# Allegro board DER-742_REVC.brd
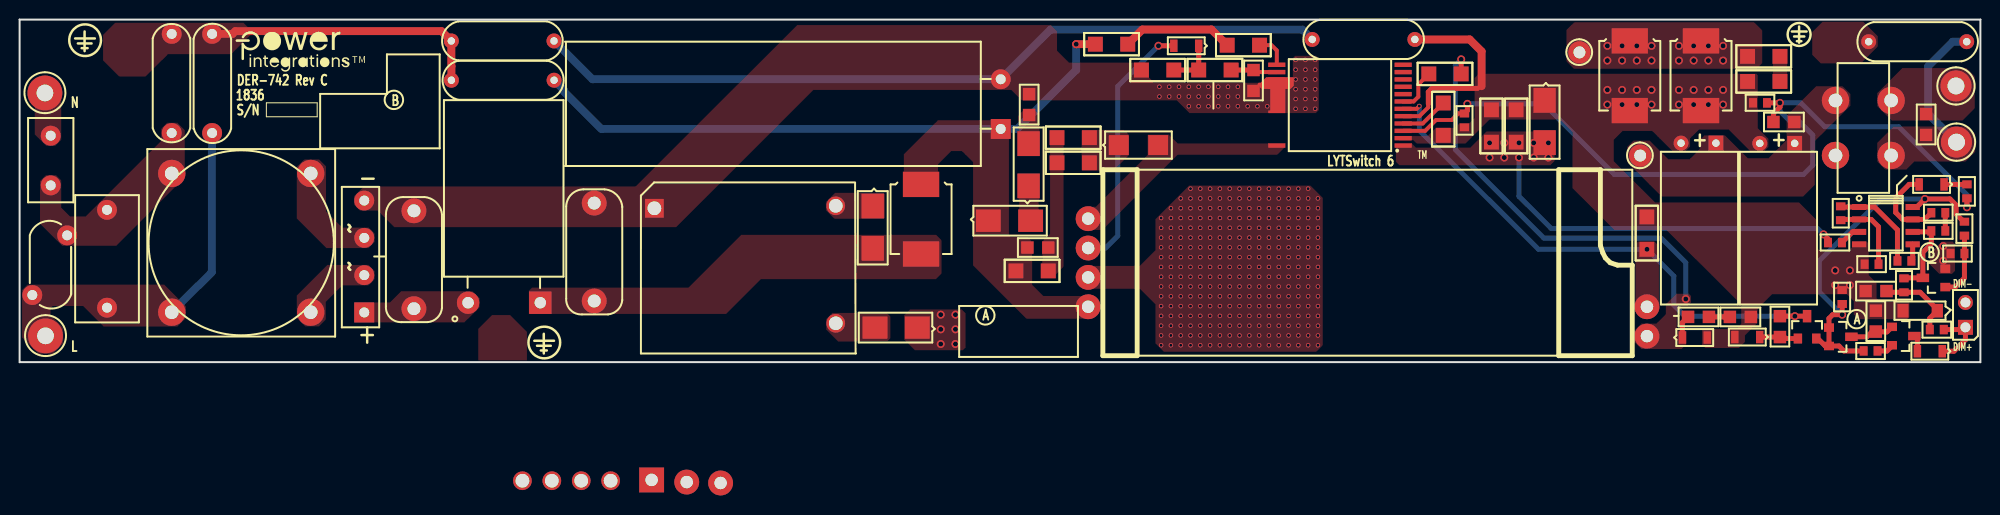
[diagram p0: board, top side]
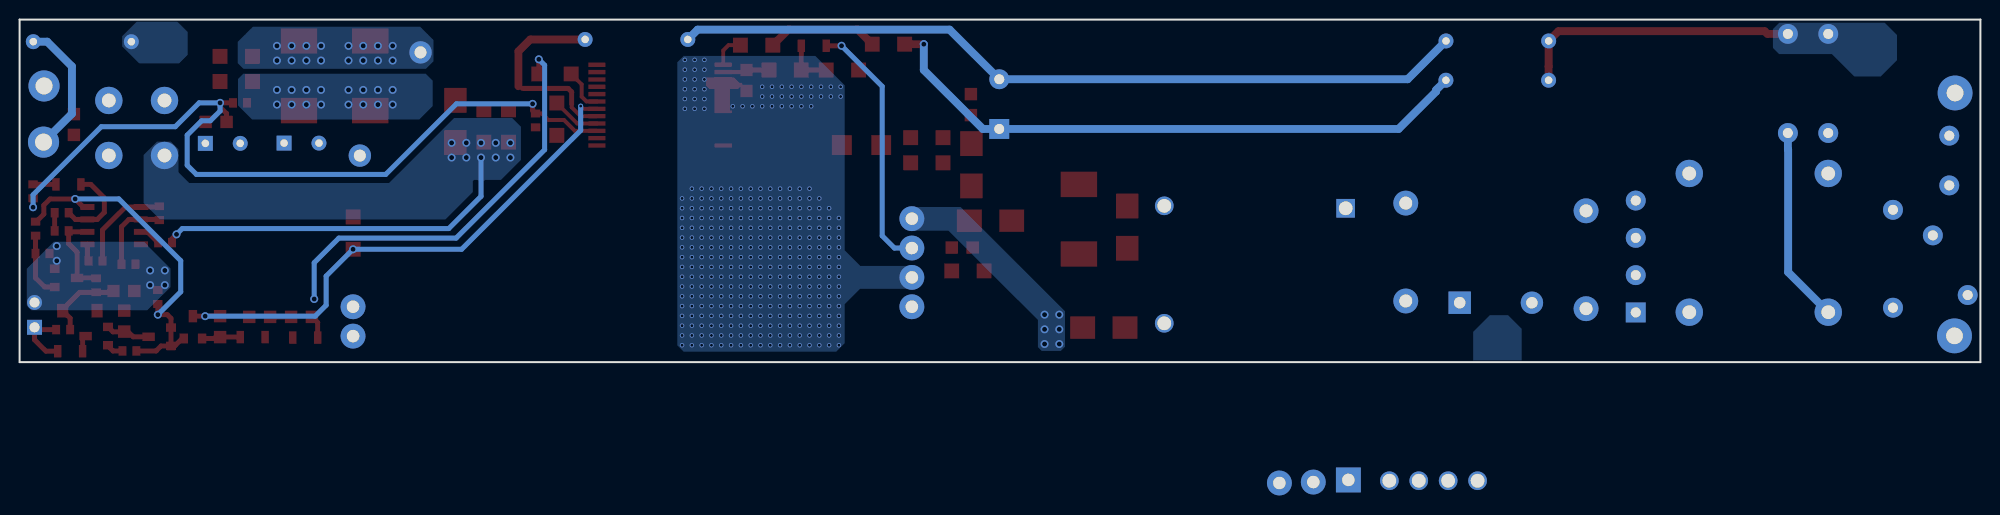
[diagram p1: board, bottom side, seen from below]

Outline 200 x 35 mm; copper layers: TOP, BOTTOM. Coordinates in mm from the lower left corner of the outline.
Outline path: 0,35 0,0 200,0 200,35 0,35

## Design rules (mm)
constraint set DEFAULT: min track width 0.508

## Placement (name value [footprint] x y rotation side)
BR1  UD4KB100-BP  [PIDAXBRIDGED3K]  35.15 5.08 90 top
C1  0.15 uF  [PINPXCAPRAD13X7LS10MMD040]  8.92 5.56 90 top
C2  220 nF  [PI_NP_CAPRAD512X299LS394D040]  40.22 5.46 90 top
C3  330 nF  [PI_NP_CAPRAD512X299LS394D040]  58.61 6.25 90 top
C4  68 uF  [PIPOLCAPCLYD500LS200040]  100.08 23.83 90 top
C9  3.3 nF  [PISMC0805]  104.92 11.71 180 top
C10  10uF  [PISMC1206]  117.73 29.84 180 top
C11  4.7 uF  [PISMC0805]  125.86 29.84 270 top
C12  2200 pF  [PINPCAPRAD9P0D10P0LS030]  132.08 32.97 0 top
C13  2.2 uF  [PISMC1206]  145.21 23.17 90 top
C14  220 pf  [PISMC1206]  179.55 28.68 180 top
C15  4.7 uF  [PISMC1206]  165.98 11.53 90 top
C16  100 uF  [PIPOLCAPCLYD320LS140030]  173.02 22.38 180 top
C18  100 uF  [PIPOLCAPCLYD320LS140030]  181.05 22.35 180 top
C19  330 pF  [PISMC0603]  147.37 23.99 90 top
C26  2.2 uF  [PISMC0805]  190.42 7.26 180 top
C28  1 uF  [PISMC0603]  196.42 13.41 180 top
C34  68 pF  [PINPYCAPRAD470X210LS380040]  19.64 23.65 90 top
C35  68 pF  [PINPYCAPRAD470X210LS380040]  15.52 33.3 270 top
C37  2.2 nF  [PISMC0805]  194.46 25.35 270 top
C38  220 pF  [PISMC0805]  174.45 4.62 0 top
C39  470 nF  [PISMC0603]  198.37 14.35 270 top
C40  100 nF  [PISMC0603]  185.9 7.37 270 top
C41  2200 pF  [PINPCAPRAD9P0D10P0LS030#2]  198.6 32.74 180 top
C42  2200 pF  [PINPCAPRAD9P0D10P0LS030]  54.28 28.8 180 top
C43  2200 pF  [PINPCAPRAD9P0D10P0LS030]  44.27 32.82 0 top
D1  ES1G-13-F  [PISMDO214AC12]  87.02 15.95 270 top
D7  BAV21WS-7-F  [PISMSOD323]  120.27 32.32 180 top
D8  S1K  [PISMDSMA]  112.12 22.18 0 top
D9  BAV16WS-7-F  [PISMSOD323]  196.29 18.16 180 top
D10  STTH3R04S  [PISMDO214AB12]  171.5 32.82 270 top
D11  BAV21WS-7-F  [PISMSOD323]  169.6 2.51 0 top
D16  S3J-13-F  [PISMDO214AB12]  91.95 18.16 270 top
D17  ES1G-13-F  [PISMDO214AC12]  91.57 3.53 180 top
D18  STTH3R04S  [PISMDO214AB12]  164.24 32.82 270 top
D19  BAV19WS  [PISMSOD323]  196.11 1.12 180 top
D21  B340A-13-F  [PISMDO214AC12]  155.55 26.75 270 top
F1  3.15 A  [PI_RST_MICROFUSE]  3.17 23.14 270 top
FL1  Hole_50mils  [PI_HOLE_50MIL]  165.3 21.1 0 top
FL2  Hole_50mils  [PI_HOLE_50MIL]  159.11 31.65 0 top
J4  CON2  [PIMOLEX2KKHEADER]  198.48 3.56 90 top
L1  20mH  [PI_IND_4P_690X512LS300X200D055#2]  20.07 16 0 top
L3  680 uh  [PI_CHOKE_RL5480-4_D2]  53.11 6.07 180 top
L4  200uH  [PI_IND_4P_690X512LS300X200D055]  185.52 27.74 0 top
NOREF  -  []  0 0 90 top
NOREF#2  -  []  22.05 34.24 0 top
NOREF#3  -  []  0 35 0 top
Q2  MMBT4401LT1G  [PISMSOT23123_1]  183.26 2.41 0 top
Q10  MMBT3906  [PISMSOT23123_1]  190.98 1.73 270 top
Q11  2N7002  [PISMSOT23123_1]  196.42 9.55 90 top
R4  2.00 M  [PISMR1206]  113.03 32.49 180 top
R14  71.5 k  [PISMR0603]  198.63 18.16 270 top
R17  120 k  [PISMR1206]  101.62 9.32 0 top
R18  10 k  [PISMR1206]  120.27 29.84 0 top
R19  1 k  [PISMR0603]  192.2 7.14 90 top
R20  20 k  [PISMR0603]  194.84 3.33 0 top
R22  47  [PISMR1206]  147.04 29.45 180 top
R23  22  [PISMR1206]  179.55 31.24 180 top
R24  0.068  [PISMR1206]  150.13 22.48 90 top
R29  100 k  [PISMR0805]  181.03 24.54 180 top
R30  3.09 k  [PISMR0603]  178.23 26.49 180 top
R34  1 k  [PISMR0603]  196.42 15.27 180 top
R45  2.00 M  [PISMR1206]  126.48 32.38 180 top
R46  20  [PISMR1206]  105.82 20.37 0 top
R47  10 k  [PISMR0805]  102.97 25.25 90 top
R50  20  [PISMR1206]  105.82 22.93 0 top
R51  0.068  [PISMR1206]  152.64 22.48 90 top
R52  22  [PISMR0805]  170.18 4.62 0 top
R62  1 k  [PISMR0603]  192.96 10.34 180 top
R63  261 k  [PISMR0603]  185.75 14.5 90 top
R64  9.1 k  [PISMR0805]  189.33 5.26 270 top
R65  5.1 k  [PISMR0603]  196.95 11.1 0 top
R66  6.34 k  [PISMR0603]  188.09 1.14 0 top
R71  909  [PISMR0603]  189.61 10.01 180 top
R73  2.21 k  [PISMR0805]  179.55 4.7 270 top
R74  909  [PISMR0603]  185.88 12.22 180 top
RTN  PCB Terminal 18 AWG  [PI_HOLE_18AWG]  197.56 22.45 0 top
RV1  275 Vac  [PIDISC350X160LS210X140040]  4.85 12.95 270 top
T1  EPC1716D  [PI_BOBBIN_EPC1716D_7P]  64.75 15.72 0 top
T2  EDR4110  [PI_BOBBIN_EDR4110_9P_6X3]  137.49 10.16 0 top
TP1  BLK  [PITPKEYSTONE125X125]  2.64 2.69 180 top
TP2  WHT  [PITPKEYSTONE125X125]  2.58 27.5 180 top
U4  LYT6068C  [PI_IC_INSOP_24D]  141.12 22.13 180 top
U8  LMV431AIMF  [PISMSOT23132]  184.56 1.65 270 top
U14  TSX712IDT  [PISMSO8]  187.63 15.85 270 top
VOUT  PCB Terminal 18 AWG  [PI_HOLE_18AWG]  197.51 28.19 0 top
VR2  1SMA200Z  [PISMDO214AC12]  98.81 14.45 0 top
VR3  1SMA200Z  [PISMDO214AC12]  102.92 18.01 90 top
VR5  BZT52C15-7-F  [PI_SM_SOD-123_12]  195.61 5.26 180 top
VR6  BZX384-B13,115  [PISMSOD323]  177.5 2.57 180 top

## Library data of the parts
BR1 = DISCRETE BRIDGE_+~~-: alternate symbols: (pidaxbridgeD3K_horz)
C1 = CAP NP: alternate symbols: (pinpxcaprad13x7LS10mmD040H)
C2 C3 = CAP NP: alternate symbols: (pi_np_caprad512x299ls394d040_h)
C4 = CAP POL: alternate symbols: (pipolcapclyd500ls2000401650lh)
C9-C15 C19 C34 C35 C37 C38 C41-C43 = CAP NP
C16 C18 = CAP POL
C26 C28 C39 C40 = CAP NP: room: 4
D1 D7-D11 D16-D19 = DIODE
D21 = DIODE SCHOTTKY
F1 = FUSE: alternate symbols: (pirstmicrofusehoz)
FL1 FL2 = FlyingLead
J4 = CON2
L1 L4 = INDUCTOR_4P_revD: alternate symbols: (pi_4p_700x400d055_horiz)
L3 = INDUCTOR_dot2: alternate symbols: (pi_choke_RL5480-4H_d2)
Q2 = NPN_BEC
Q10 = PNP_BEC
Q11 = FET_N_GSD
R4 R17 R18 R22-R24 R29 R30 R45-R47 R50-R52 R64 R66 R73 = R
R14 R19 R20 R34 R62 R63 R65 R71 R74 = R: room: 1
RTN VOUT = TERM_1Pin
RV1 = VARISTOR: alternate symbols: (pi_disc_354x220_ls220x10_040_h)
T1 = BEFD18_7P
T2 = BEQ20_9P
TP1 TP2 = TESTPOINT
U4 = LYT6
U8 = TL431/SOT-23_RCA
U14 = TSX712IDT
VR2 VR3 VR5 VR6 = DIODE_ZENER

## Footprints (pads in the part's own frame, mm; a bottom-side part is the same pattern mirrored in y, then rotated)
PI_BOBBIN_EDR4110_9P_6X3
  rect 2.54x2.54 hole 1.27: 1(-73.026,-22.193)
  round 2.54 hole 1.27: 2(-28.5,4.5) 3(-28.5,1.5) 4(-28.5,-1.5) 5(-28.5,-4.5) 6(-69.445,-22.41) 7(28.5,-7.5) 8(28.5,-4.5) 9(-65.988,-22.506)
PI_BOBBIN_EPC1716D_7P
  rect 1.905x1.905 hole 1.397: 1(0,0)
  round 1.905 hole 1.397: 2(-13.46,-27.836) 3(-10.46,-27.836) 4(-7.46,-27.836) 5(-4.46,-27.836) 6(18.5,-11.75) 7(18.5,0.25)
PI_CHOKE_RL5480-4_D2
  rect 2.286x2.286 hole 1.168: 1(0,0)
  round 2.286 hole 1.168: 2(7.366,0)
PI_HOLE_18AWG
  round 3.175 hole 1.727: 1(0,0.025)
PI_HOLE_50MIL
  round 2.286 hole 1.219: 1(0,0)
PI_IC_INSOP_24D
  rect 1.75x0.45 smd: 1(0,0) 2(0,-0.75) 3(0,-1.5) 4(0,-2.25) 5(0,-3) 6(0,-3.75) 7(0,-4.5) 8(0,-5.25) 9(0,-6) 10(0,-6.75) 11(0,-7.5) 12(0,-8.25) 13(12.89,-8.25) 14(12.89,-7.5) 15(12.89,-6.75) 24(12.89,0)
  custom 0.438x0.438 smd: 16(12.89,-4.67)
PI_IND_4P_690X512LS300X200D055
  round 2.794 hole 1.397: 1(-0.3,-1) 2(5.38,-1) 3(5.38,-6.62) 4(-0.3,-6.62)
PI_IND_4P_690X512LS300X200D055#2
  round 2.794 hole 1.397: 1(-4.547,3.277) 2(9.627,3.277) 3(9.627,-10.897) 4(-4.547,-10.897)
PI_NP_CAPRAD512X299LS394D040
  round 2.54 hole 1.321: 1(0,0) 2(10,0)
PI_RST_MICROFUSE
  round 2.032 hole 1.016: 1(0,0) 2(5.08,0)
PI_SM_SOD-123_12
  rect 1.143x1.397 smd: 1(0,0) 2(3.505,0)
PIDAXBRIDGED3K
  rect 2.032x2.032 hole 1.016: 1(0,0)
  round 2.032 hole 1.016: 2(3.81,0) 3(7.62,0) 4(11.43,0)
PIDISC350X160LS210X140040
  round 2.032 hole 1.016: 1(0,0) 2(6.096,-3.556)
PIMOLEX2KKHEADER
  rect 1.524x1.524 hole 1.016: 1(0,0)
  round 1.524 hole 1.016: 2(2.54,0)
PINPCAPRAD9P0D10P0LS030
  round 1.524 hole 0.762: 1(-0.236,0) 2(10.236,0)
PINPCAPRAD9P0D10P0LS030#2
  round 1.524 hole 0.762: 1(0,0) 2(10,0)
PINPXCAPRAD13X7LS10MMD040
  round 2.032 hole 1.016: 1(0,0) 2(10,0)
PINPYCAPRAD470X210LS380040
  round 2.032 hole 1.016: 1(-0.236,0) 2(9.888,0)
PIPOLCAPCLYD320LS140030
  rect 1.524x1.524 hole 0.762: 1(0,0)
  round 1.524 hole 0.762: 2(3.556,0)
PIPOLCAPCLYD500LS200040
  rect 2.032x2.032 hole 1.016: 1(0,0)
  round 2.032 hole 1.016: 2(5.08,0)
PISMC0603
  rect 0.813x0.965 smd: 1(0,0) 2(1.422,0)
PISMC0805
  rect 1.27x1.27 smd: 1(0,0) 2(2.134,0)
PISMC1206
  rect 1.524x1.524 smd: 1(0,0) 2(3.302,0)
PISMDO214AB12
  rect 2.591x3.708 smd: 1(0,0) 2(7.112,0)
PISMDO214AC12
  rect 2.54x2.286 smd: 1(0,0) 2(4.318,0)
PISMDSMA
  rect 2.032x2.032 smd: 1(0,0) 2(4.013,0)
PISMR0603
  rect 0.813x0.965 smd: 1(0,0) 2(1.422,0)
PISMR0805
  rect 1.27x1.27 smd: 1(0,0) 2(2.134,0)
PISMR1206
  rect 1.524x1.524 smd: 1(0,0) 2(3.302,0)
PISMSO8
  rect 0.61x1.448 smd: 1(0,0) 2(1.27,0) 3(2.54,0) 4(3.81,0) 5(3.81,5.461) 6(2.54,5.461) 7(1.27,5.461) 8(0,5.461)
PISMSOD323
  rect 0.762x1.27 smd: 1(0,0) 2(2.54,0)
PISMSOT23123_1
  rect 0.864x1.016 smd: 1(-1.88,0) 2(0,0)
  rect 0.864x1.27 smd: 3(-0.94,2.286)
PISMSOT23132
  rect 0.864x1.016 smd: 1(-1.88,0) 2(0,0)
  rect 0.864x1.27 smd: 3(-0.94,2.286)
PITPKEYSTONE125X125
  round 3.556 hole 1.702: 1(0,0)

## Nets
GND: C12.2 C13.1 C14.2 C15.2 C16.2 C18.2 C19.1 C26.2 C38.2 C40.1 D10.2 D11.2 D18.2 D21.1 J4.2 Q11.2(S) R24.2 R30.2 R51.2 R64.1 R65.1 R71.2 U4.2 U4.5 U14.4 VR5.2 VR6.2
GND_EARTH: C34.2 C35.1 C41.2 C42.2 C43.1
NC8: U4.8
NC9: U4.9
NC10: U4.10
NC11: U4.11
NC12: U4.12
NC15: U4.15
PIN7: D11.1 R22.1 R52.1 T2.7
PIN8: C15.1 Q2.3 R73.1 T2.8 U4.6
PWM: D19.1 J4.1 R20.2
V_AUX: C39.1 C40.2 Q2.2(EMITTER) R66.1 U8.1(VREF) U8.2 U14.8
N10967118: C10.1 D7.1 R18.1
N10967192: D8.1 R46.2 R50.2
N10967272: D8.2 D17.1 T2.2 U4.24
N10967292: C4.1 C9.2 C42.1 D16.1 R4.2 R17.1 T2.5 VR2.1
N10967352: C11.1 R18.2 U4.14
N10967360: C19.2 R14.2 R29.2 R30.1 U4.3
N10967588: C16.1 C18.1 FL1.1 L4.1 R29.1
N10967616: D10.1 D18.1 FL2.1 R23.2
N10968210: C14.1 R23.1
N10968562: BR1.4 C2.2 C3.2 C4.2 C10.2 C11.2 C12.1 C43.2 R47.2 T1.1 T2.4 U4.16
N10970513: C1.2 C35.2 F1.2 L1.1 RV1.1
N10971255: BR1.3(AC2) L1.2
N10975943: C9.1 R17.2 R46.1 R50.1
N11207739: C1.1 C34.1 L1.4 RV1.2 TP1.1
N11231482: R22.2 U4.7
N11317958: R45.1 U4.13(VPIN)
N11319179: C13.2 U4.4
N11446006: D1.1 T1.7
N11450999: C3.1 D1.2 D16.2 L3.1
N11459929: BR1.1 C2.1 L3.2
N11465077: F1.1 TP2.1
N11478809: VR2.2 VR3.1
N11478836: R47.1 VR3.2
N11497112: C38.1 R52.2
N11921550: Q10.2(EMITTER) R66.2
N11921594: Q10.1 R64.2 U8.3
N11921660: C39.2 Q11.1 R65.2
N11921664: D19.2 Q10.3
N11921668: D9.2 R34.2 U14.7(OUT)
N11921676: C28.1 R34.1
N11921680: C28.2 Q11.3 R19.2 U14.6
N11921778: R62.1 U14.5
N11921790: D9.1 R14.1
N11921854: C26.1 R19.1 R20.1 VR5.1
N11922118: R62.2 R63.2 U14.1
N11922154: R63.1 R71.1 U14.2
N11926287: C37.1 L4.2 VOUT.1
N11926309: C37.2 C41.1 L4.3 RTN.1
N11929315: R4.1 R45.2
N11931425: D7.2 T2.3
N11945881: D21.2 L4.4 R24.1 R51.1 R74.2 U4.1
N11960452: R74.1 U14.3
N12237167: D17.2 T1.6
N12249644: Q2.1 R73.2 VR6.1
N12296601: BR1.2 L1.3

Pads without a net: T1 2 3 4 5; T2 1 6 9

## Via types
v1: diameter 0.813, hole 0.508, TOP to BOTTOM, 66 vias
v2: diameter 0.457, hole 0.305, TOP to BOTTOM, 328 vias

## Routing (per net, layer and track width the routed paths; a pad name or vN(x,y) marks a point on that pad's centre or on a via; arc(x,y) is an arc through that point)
GND: length 20.6
  TOP w0.4: U4.5 142.79,25.13 143.69,26.04 143.69,26.39
  TOP w0.508: 148.72,27.97 144.04,27.97 143.69,27.61 143.69,26.39
  TOP w0.8: C12.2 147.9,32.97 149.12,31.75 149.12,28.19
  vias: v1(161.95,27.81) v1(161.95,26.31) v1(163.45,27.81) v1(163.45,26.31) v1(164.95,27.81) v1(164.95,26.31) v1(166.45,27.81) v1(166.45,26.31) v1(169.25,27.81) v1(169.25,26.31) v1(170.75,27.81) v1(170.75,26.31) v1(172.25,27.81) v1(172.25,26.31) v1(173.75,27.81) v1(173.75,26.31) v1(185.19,9.37) v1(185.19,7.87) v1(186.69,9.37) v1(186.69,7.87) v1(196.21,11.86) v1(196.21,10.36)
GND_EARTH: length 28.9
  TOP w0.8: C34.2 21.72,33.54 22,33.82 43.03,33.82 C43.1 44.04,30.23 44.04,30.22 C42.2
PIN7: length 45.3
  TOP w0.508: R52.1 169.6,4.04 D11.1 ; v1(147.04,30.94) R22.1
  BOTTOM w0.508: v1(169.95,6.45) 169.95,10.16 167.44,12.67 155.47,12.67 146.45,21.7 146.45,30.34 v1(147.04,30.94)
PIN8: length 54.9
  TOP w0.4: v2(142.77,26.16) 142.49,25.88 U4.6
  TOP w0.508: Q2.3 v1(181.08,4.7) R73.1
  BOTTOM w0.508: v2(142.77,26.16) 142.77,23.67 154.91,11.53 v1(165.99,11.53) 168.73,8.79 168.73,5.82 169.85,4.7 v1(181.08,4.7)
PWM: length 6.4
  TOP w0.508: D19.1 197.3,1.12 198.48,2.29 J4.1 198.24,3.33 R20.2
V_AUX: length 37.8
  TOP w0.508: U8.2 184.18,1.65 183.41,2.41 Q2.2 ; U8.2 185.57,1.65 186.08,1.14 R66.1 ; U8.2 U8.1 184.56,4.47 184.94,4.85 v1(185.9,4.85) C40.2 ; U14.8 193.51,15.85 v1(194.34,16.68) 196.89,16.68 197.53,16.04 197.53,15.12 198.3,14.35 C39.1
  BOTTOM w0.508: v1(185.9,4.85) 183.57,7.19 183.57,10.36 189.88,16.68 v1(194.34,16.68)
N10967118: length 5
  TOP w0.508: C10.1 R18.1 D7.1
N10967272:
  vias: v1(93.95,4.85) v1(93.95,3.35) v1(93.95,1.85) v1(95.45,4.85) v1(95.45,3.35) v1(95.45,1.85)
N10967292: length 62.5
  TOP w0.8: R4.2 v1(107.77,32.49)
  BOTTOM w0.8: C42.1 55.52,27.8 55.52,27.65 59.34,23.83 C4.1 101.75,23.83 107.77,29.85 v1(107.77,32.49)
N10967352: length 4.7
  TOP w0.4: U4.14 126.07,29.63 C11.1
  TOP w0.508: C11.1 R18.2
N10967360: length 83.7
  TOP w0.4: U4.3 143.37,23.63 144.48,24.74 146.08,24.74 146.75,25.41 C19.2
  TOP w0.508: C19.2 147.68,25.71 v1(147.68,26.39) ; R30.1 v1(179.55,26.49) 179.55,26.06 178.89,25.4 R29.2 ; R14.2 v1(198.63,15.82)
  BOTTOM w0.508: v1(198.63,15.82) 198.63,17.09 191.67,24.05 184.12,24.05 181.69,26.49 v1(179.55,26.49) 179.55,25.65 180.54,24.66 181.43,24.66 182.91,23.19 182.91,20.12 181.97,19.18 162.66,19.18 155.45,26.39 v1(147.68,26.39)
N10967616:
  vias: v1(161.95,32.31) v1(161.95,30.81) v1(163.45,32.31) v1(163.45,30.81) v1(164.95,32.31) v1(164.95,30.81) v1(166.45,32.31) v1(166.45,30.81) v1(169.25,32.31) v1(169.25,30.81) v1(170.75,32.31) v1(170.75,30.81) v1(172.25,32.31) v1(172.25,30.81) v1(173.75,32.31) v1(173.75,30.81)
N10968562: length 81.5
  BOTTOM w0.8: C43.2 58.42,28.91 C4.2 105.14,33.97 130.84,33.97 C12.1
  vias: v2(116.26,28.14) v2(116.26,27.14) v2(116.43,14.73) v2(116.43,13.73) v2(116.43,12.73) v2(116.43,11.73) v2(116.43,10.73) v2(116.43,9.73) v2(116.43,8.73) v2(116.43,7.73) v2(116.43,6.73) v2(116.43,5.73) v2(116.43,4.73) v2(116.43,3.73) v2(116.43,2.73) v2(116.43,1.73) v2(117.26,28.14) v2(117.26,27.14) v2(117.43,15.73) v2(117.43,14.73) v2(117.43,13.73) v2(117.43,12.73) v2(117.43,11.73) v2(117.43,10.73) v2(117.43,9.73) v2(117.43,8.73) v2(117.43,7.73) v2(117.43,6.73) v2(117.43,5.73) v2(117.43,4.73) v2(117.43,3.73) v2(117.43,2.73) v2(117.43,1.73) v2(118.26,28.14) v2(118.26,27.14) v2(118.43,16.73) v2(118.43,15.73) v2(118.43,14.73) v2(118.43,13.73) v2(118.43,12.73) v2(118.43,11.73) v2(118.43,10.73) v2(118.43,9.73) v2(118.43,8.73) v2(118.43,7.73) v2(118.43,6.73) v2(118.43,5.73) v2(118.43,4.73) v2(118.43,3.73) v2(118.43,2.73) v2(118.43,1.73) v2(119.26,28.14) v2(119.26,27.14) v2(119.26,26.14) v2(119.43,17.73) v2(119.43,16.73) v2(119.43,15.73) v2(119.43,14.73) v2(119.43,13.73) v2(119.43,12.73) v2(119.43,11.73) v2(119.43,10.73) v2(119.43,9.73) v2(119.43,8.73) v2(119.43,7.73) v2(119.43,6.73) v2(119.43,5.73) v2(119.43,4.73) v2(119.43,3.73) v2(119.43,2.73) v2(119.43,1.73) v2(120.26,28.14) v2(120.26,27.14) v2(120.26,26.14) v2(120.43,17.73) v2(120.43,16.73) v2(120.43,15.73) v2(120.43,14.73) v2(120.43,13.73) v2(120.43,12.73) v2(120.43,11.73) v2(120.43,10.73) v2(120.43,9.73) v2(120.43,8.73) v2(120.43,7.73) v2(120.43,6.73) v2(120.43,5.73) v2(120.43,4.73) v2(120.43,3.73) v2(120.43,2.73) v2(120.43,1.73) v2(121.26,28.14) v2(121.26,27.14) v2(121.26,26.14) v2(121.43,17.73) v2(121.43,16.73) v2(121.43,15.73) v2(121.43,14.73) v2(121.43,13.73) v2(121.43,12.73) v2(121.43,11.73) v2(121.43,10.73) v2(121.43,9.73) v2(121.43,8.73) v2(121.43,7.73) v2(121.43,6.73) v2(121.43,5.73) v2(121.43,4.73) v2(121.43,3.73) v2(121.43,2.73) v2(121.43,1.73) v2(122.26,28.14) v2(122.26,27.14) v2(122.26,26.14) v2(122.43,17.73) v2(122.43,16.73) v2(122.43,15.73) v2(122.43,14.73) v2(122.43,13.73) v2(122.43,12.73) v2(122.43,11.73) v2(122.43,10.73) v2(122.43,9.73) v2(122.43,8.73) v2(122.43,7.73) v2(122.43,6.73) v2(122.43,5.73) v2(122.43,4.73) v2(122.43,3.73) v2(122.43,2.73) v2(122.43,1.73) v2(123.26,28.14) v2(123.26,27.14) v2(123.26,26.14) v2(123.43,17.73) v2(123.43,16.73) v2(123.43,15.73) v2(123.43,14.73) v2(123.43,13.73) v2(123.43,12.73) v2(123.43,11.73) v2(123.43,10.73) v2(123.43,9.73) v2(123.43,8.73) v2(123.43,7.73) v2(123.43,6.73) v2(123.43,5.73) v2(123.43,4.73) v2(123.43,3.73) v2(123.43,2.73) v2(123.43,1.73) v2(124.26,28.14) v2(124.26,27.14) v2(124.26,26.14) v2(124.43,17.73) v2(124.43,16.73) v2(124.43,15.73) v2(124.43,14.73) v2(124.43,13.73) v2(124.43,12.73) v2(124.43,11.73) v2(124.43,10.73) v2(124.43,9.73) v2(124.43,8.73) v2(124.43,7.73) v2(124.43,6.73) v2(124.43,5.73) v2(124.43,4.73) v2(124.43,3.73) v2(124.43,2.73) v2(124.43,1.73) v2(125.26,26.14) v2(125.43,17.73) v2(125.43,16.73) v2(125.43,15.73) v2(125.43,14.73) v2(125.43,13.73) v2(125.43,12.73) v2(125.43,11.73) v2(125.43,10.73) v2(125.43,9.73) v2(125.43,8.73) v2(125.43,7.73) v2(125.43,6.73) v2(125.43,5.73) v2(125.43,4.73) v2(125.43,3.73) v2(125.43,2.73) v2(125.43,1.73) v2(126.26,26.14) v2(126.43,17.73) v2(126.43,16.73) v2(126.43,15.73) v2(126.43,14.73) v2(126.43,13.73) v2(126.43,12.73) v2(126.43,11.73) v2(126.43,10.73) v2(126.43,9.73) v2(126.43,8.73) v2(126.43,7.73) v2(126.43,6.73) v2(126.43,5.73) v2(126.43,4.73) v2(126.43,3.73) v2(126.43,2.73) v2(126.43,1.73) v2(127.26,26.14) v2(127.43,17.73) v2(127.43,16.73) v2(127.43,15.73) v2(127.43,14.73) v2(127.43,13.73) v2(127.43,12.73) v2(127.43,11.73) v2(127.43,10.73) v2(127.43,9.73) v2(127.43,8.73) v2(127.43,7.73) v2(127.43,6.73) v2(127.43,5.73) v2(127.43,4.73) v2(127.43,3.73) v2(127.43,2.73) v2(127.43,1.73) v2(128.43,17.73) v2(128.43,16.73) v2(128.43,15.73) v2(128.43,14.73) v2(128.43,13.73) v2(128.43,12.73) v2(128.43,11.73) v2(128.43,10.73) v2(128.43,9.73) v2(128.43,8.73) v2(128.43,7.73) v2(128.43,6.73) v2(128.43,5.73) v2(128.43,4.73) v2(128.43,3.73) v2(128.43,2.73) v2(128.43,1.73) v2(129.43,17.73) v2(129.43,16.73) v2(129.43,15.73) v2(129.43,14.73) v2(129.43,13.73) v2(129.43,12.73) v2(129.43,11.73) v2(129.43,10.73) v2(129.43,9.73) v2(129.43,8.73) v2(129.43,7.73) v2(129.43,6.73) v2(129.43,5.73) v2(129.43,4.73) v2(129.43,3.73) v2(129.43,2.73) v2(129.43,1.73) v2(130.15,30.88) v2(130.15,29.88) v2(130.15,28.88) v2(130.15,27.88) v2(130.15,26.88) v2(130.15,25.88) v2(130.43,17.73) v2(130.43,16.73) v2(130.43,15.73) v2(130.43,14.73) v2(130.43,13.73) v2(130.43,12.73) v2(130.43,11.73) v2(130.43,10.73) v2(130.43,9.73) v2(130.43,8.73) v2(130.43,7.73) v2(130.43,6.73) v2(130.43,5.73) v2(130.43,4.73) v2(130.43,3.73) v2(130.43,2.73) v2(130.43,1.73) v2(131.15,30.88) v2(131.15,29.88) v2(131.15,28.88) v2(131.15,27.88) v2(131.15,26.88) v2(131.15,25.88) v2(131.43,17.73) v2(131.43,16.73) v2(131.43,15.73) v2(131.43,14.73) v2(131.43,13.73) v2(131.43,12.73) v2(131.43,11.73) v2(131.43,10.73) v2(131.43,9.73) v2(131.43,8.73) v2(131.43,7.73) v2(131.43,6.73) v2(131.43,5.73) v2(131.43,4.73) v2(131.43,3.73) v2(131.43,2.73) v2(131.43,1.73) v2(132.15,30.88) v2(132.15,29.88) v2(132.15,28.88) v2(132.15,27.88) v2(132.15,26.88) v2(132.15,25.88) v2(132.43,16.73) v2(132.43,15.73) v2(132.43,14.73) v2(132.43,13.73) v2(132.43,12.73) v2(132.43,11.73) v2(132.43,10.73) v2(132.43,9.73) v2(132.43,8.73) v2(132.43,7.73) v2(132.43,6.73) v2(132.43,5.73) v2(132.43,4.73) v2(132.43,3.73) v2(132.43,2.73) v2(132.43,1.73)
N11207739: length 20
  BOTTOM w0.8: C34.1 19.64,21.74 19.61,21.72 19.61,9.2 L1.4
N11231482: length 4.5
  TOP w0.4: R22.2 142.67,28.38 142.67,27.12 142.19,26.63 U4.7
N11317958: length 3.4
  TOP w0.4: U4.13 128.23,31.84 127.69,32.38 R45.1
N11319179: length 5
  TOP w0.4: C13.2 143.12,24.38 U4.4
N11497112: length 2.1
  TOP w0.508: R52.2 173.84,4.62 C38.1
N11921550: length 1.8
  TOP w0.508: R66.2 190.47,1.14 190.98,1.65 Q10.2
N11921594: length 4.6
  TOP w0.508: U8.3 188.42,2.59 188.93,3.1 189.31,3.1 R64.2 189.36,3.1 190.47,3.1 Q10.1
N11921660: length 6.7
  TOP w0.508: Q11.1 197.43,7.67 198.37,8.61 R65.2 C39.2
N11921664: length 1.7
  TOP w0.508: D19.2 193.57,2.36 Q10.3
N11921668: length 8.7
  TOP w0.508: D9.2 192.74,18.16 191.36,16.79 191.36,15.29 192.07,14.58 U14.7 194.31,14.58 R34.2
N11921676: length 1.9
  TOP w0.508: R34.1 C28.1
N11921680: length 9.1
  TOP w0.508: U14.6 194.89,13.31 C28.2 195,12.09 194.13,11.23 Q11.3 192.25,8.61 R19.2
N11921778: length 1.8
  TOP w0.508: R62.1 193.09,10.46 U14.5
N11921790: length 2.3
  TOP w0.508: R14.1 D9.1
N11921854: length 8.3
  TOP w0.508: R20.1 194.84,4.5 VR5.1 195.61,5.38 193.85,7.14 R19.1 190.55,7.14 C26.1
N11922118: length 10
  TOP w0.508: R62.2 191.54,13.51 189.2,15.85 U14.1 185.83,15.85 R63.2
N11922154: length 8
  TOP w0.508: R63.1 185.83,14.58 U14.2 188.86,14.58 189.61,13.83 R71.1
N11926309: length 13.9
  BOTTOM w0.8: RTN.1 194.67,25.37 194.67,30.22 197.19,32.74 C41.1
N11929315: length 11.4
  TOP w0.8: R45.2 121.57,33.99 114.53,33.99 R4.1
N11931425: length 26.2
  TOP w0.508: D7.2 v1(116.16,32.32)
  BOTTOM w0.508: v1(116.16,32.32) 112.01,28.18 112.01,12.91 110.77,11.66 T2.3
N11945881: length 37.7
  TOP w0.508: R74.2 184.45,12.6 v1(184,13.06)
  BOTTOM w0.508: v1(184,13.06) 183.4,13.65 156.23,13.65 152.94,16.94 v1(152.94,20.9)
  vias: v1(149.94,22.4) v1(149.94,20.9) v1(151.44,22.4) v1(151.44,20.9) v1(152.94,22.4) v1(154.44,22.4) v1(154.44,20.9) v1(155.94,22.4) v1(155.94,20.9)
N11960452: length 2.2
  TOP w0.508: U14.3 186.97,13.31 R74.1
N12249644: length 3.9
  TOP w0.508: VR6.1 R73.2 179.98,2.57 180.14,2.41 Q2.1

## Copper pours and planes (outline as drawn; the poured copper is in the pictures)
GND on TOP: 140.64,22.68 142.16,22.68 142.52,22.33 147.47,22.33 149.94,24.79 157.12,24.79 158.39,23.52 158.39,17.78 162.66,13.51 167.97,13.51 175.62,5.87 175.62,3.91 175.08,3.38 171.78,3.38 171.6,3.2 171.6,1.78 171.93,1.45 175.36,1.45 175.98,2.07 175.98,2.73 177.27,4.01 177.27,5.46 178.74,6.93 186.39,6.93 187.08,6.24 187.08,4.89 187.58,4.39 192.56,4.39 192.76,4.6 192.76,6.07 192.56,6.27 189.66,6.27 189.41,6.53 189.41,8.08 188.62,8.86 188.62,12.09 188.37,12.34 186.89,12.34 186.89,11.71 186.51,11.33 183.67,11.33 183.26,11.73 183.26,14.55 181.51,16.31 166.83,16.31 162.61,20.52 162.61,22.73 163.5,23.62 166.52,23.62 168.63,21.51 169.88,21.51 170.38,22.02 170.38,22.86 171.3,23.77 174.32,23.77 176.58,21.51 177.9,21.51 178.37,21.98 178.37,22.82 177.29,23.9 177.29,29.31 177.14,29.46 148.84,29.46 148.41,29.03 148.41,24.94 147.88,24.41 146.89,24.41 146.41,23.93 144.45,23.93 143.61,23.09 140.61,23.09 140.54,23.01 140.54,22.78
GND on TOP: 196.06,12.32 197.15,12.32 197.41,12.06 197.41,9.32 197.1,9.02 195.81,9.02 194.84,9.98 194.84,11.1
GND on BOTTOM: 184.61,7.67 186.97,5.31 198.81,5.31 199.26,5.77 199.26,9.55 196.52,12.29 187.32,12.29 184.61,9.58
GND on BOTTOM: 177.19,29.46 158.57,29.46 157.86,28.75 157.86,26.16 159.23,24.79 176.28,24.79 177.72,26.24 177.72,28.93
GND_EARTH on TOP: 22.83,34.67 9.75,34.67 8.51,33.43 8.51,30.84 10.16,29.18 12.85,29.18 15.14,31.47 21.59,31.47 23.57,33.45 23.57,33.93
GND_EARTH on TOP, BOTTOM: 188.06,34.77 183.9,34.77 182.85,33.73 182.85,31.39 183.72,30.53 187.81,30.53 189.53,32.26 189.53,33.3
GND_EARTH on BOTTOM: 20.52,34.67 9.75,34.67 8.51,33.43 8.51,30.84 10.16,29.18 12.85,29.18 15.14,31.47 20.52,31.47 21.16,32.11 21.16,34.04
Net_3 on BOTTOM: 46.79,0.18 51.74,0.18 51.74,3.1 50.04,4.8 48.18,4.8 46.79,3.4
Net_4 on TOP: 46.79,0.18 51.74,0.18 51.74,3.1 50.04,4.8 48.18,4.8 46.79,3.4
PIN7 on TOP: 166.95,3.94 165.43,3.94 164.67,3.17 164.67,2.11 165.43,1.35 169.52,1.35 170.03,1.85 170.03,3.15 169.96,3.21 169.13,3.21 169.04,3.3 169.04,5.28 169.49,5.74 170.13,5.74 170.48,6.1 170.48,6.76 170.26,6.99 168.99,6.99 167.92,5.92 167.92,4.9
PIN8 on TOP: 167.21,5.49 167.21,11.86 166.75,12.32 165.07,12.32 164.82,12.06 164.82,5.41 165.48,4.75 166.47,4.75
N10967192 on TOP: 108.38,23.72 112.65,23.72 113.16,23.22 113.16,21.16 111.58,19.58 108.36,19.58 108.33,19.61 108.33,23.67
N10967272 on TOP: 128.91,22.35 118.11,22.35 117.22,23.24 115.11,23.24 115.06,23.19 115.06,21.16 109.78,15.88 108.66,15.88 108.05,15.27 108.05,14.12 108.66,13.51 110.44,13.51 118.11,21.18 128.27,21.18 129.06,21.97 129.06,22.2
N10967272 on TOP: 96.22,1.22 96.49,1.5 96.49,4.98 96.09,5.38 90.83,5.38 90.22,4.78 90.22,2.31 91.31,1.22
N10967272 on BOTTOM: 109.27,15.85 104.01,15.85 93.37,5.21 93.37,1.57 93.8,1.14 95.73,1.14 96.14,1.55 96.14,4.32 105.26,13.44 109.22,13.44 109.93,14.15 109.93,15.19
N10967292 on TOP: 109.27,6.76 104.42,6.76 103.28,7.9 103.28,12.29 102.79,12.78 101.09,12.78 100.91,12.95 100.91,24.36 100.56,24.71 93.68,24.71 90.2,21.23 90.2,17.32 90.55,16.97 93.29,16.97 93.68,17.35 93.68,20.22 95.02,21.56 96.11,21.56 97.26,20.42 97.26,9.88 102.69,4.45 109.17,4.45 109.8,5.08 109.8,6.22
N10967588 on TOP: 171.37,22.68 171.86,23.16 173.94,23.16 176.28,20.83 178.38,20.83 180.24,22.68 180.24,25.17 183.26,28.19 185.93,28.19 186.74,27.38 186.74,26.21 183.11,22.58 183.11,18.11 181.93,16.93 167.47,16.93 163.98,20.42 163.98,22 164.62,22.63 166.27,22.63 168.17,20.73 170.33,20.73 171.37,21.77
N10967616 on TOP: 177.16,29.97 158.55,29.97 157.78,30.73 157.78,33.93 158.57,34.72 176.91,34.72 177.75,33.88 177.75,30.56
N10967616 on BOTTOM: 177.16,29.97 158.55,29.97 157.78,30.73 157.78,32.92 159.13,34.26 176.2,34.26 177.75,32.72 177.75,30.56
N10968210 on TOP: 178.84,31.75 178.84,28.19 179.04,27.99 180.09,27.99 180.29,28.19 180.29,31.78 180.11,31.95 179.04,31.95
N10968562 on TOP (solid shape): 129.97,28.24 129.64,27.91 126.7,27.91 126.29,28.32 126.29,28.45 126.39,28.55 126.59,28.55 127.15,29.11 129.97,29.11
N10968562 on TOP: 108.71,9.83 114.25,9.83 115.85,11.43 115.85,14.61 119.28,18.03 131.67,18.03 132.92,16.79 132.92,1.73 132.26,1.07 116.71,1.07 115.85,1.93 115.85,5.92 114.27,7.49 108.64,7.49 108.05,8.08 108.05,9.17
N10968562 on TOP: 129.34,28.17 126.85,28.17 126.47,28.55 115.72,28.55 115.19,29.08 115.19,30.61 107.04,30.61 105.82,31.83 105.82,33.83 105.21,34.44 79.32,34.44 62.84,17.96 35.13,17.96 34.11,16.94 34.11,16.1 34.72,15.49 36.53,15.49 38.23,13.79 66.95,13.79 80.98,27.81 101.14,27.81 102.21,26.75 118.03,26.75 119.33,25.45 132.21,25.45 132.51,25.76 132.51,31.04 132.26,31.29 130.1,31.29 129.87,31.06 129.87,28.7
N10968562 on BOTTOM: 132.26,31.29 118.85,31.29 115.85,28.3 115.85,11.43 114.25,9.83 108.71,9.83 108.05,9.17 108.05,8.08 108.64,7.49 114.27,7.49 115.85,5.92 115.85,1.93 116.71,1.07 132.26,1.07 132.92,1.73 132.92,30.63
N10970513 on TOP: 2.08,18.49 2.08,14.15 4.34,11.89 9.86,11.89 16.84,18.87 16.84,23.7 16.08,24.46 15.06,24.46 14.45,23.85 14.45,22.61 6.73,14.88 5.13,14.88 4.24,15.77 4.24,18.57 3.71,19.1 2.69,19.1
N10971255 on TOP: 32.92,13.74 35.15,13.74 35.61,13.74 36.2,13.16 36.2,12.27 35.59,11.66 31.29,11.66 28.27,14.68 28.27,19.94 29.03,20.7 30.56,20.7 31.25,20 31.25,15.41
N10975943 on TOP: 105.11,23.29 105.11,13.11 104.32,12.32 104.32,8.92 104.52,8.71 105.44,8.71 106.48,9.75 106.48,23.37 106.22,23.62 105.44,23.62
N11207739 on TOP: 3.4,0.86 1.91,0.86 0.25,2.51 0.25,7.37 0.81,7.92 14.73,7.92 16.97,5.69 16.97,4.52 16.08,3.63 8.59,3.63 6.48,5.74 3.38,5.74 3.15,5.51 3.15,4.8 4.45,3.51 4.45,1.91
N11446006 on TOP: 88.16,14.66 83.11,14.66 82.25,15.52 82.25,16.36 83.19,17.3 88.11,17.3 88.27,17.14 88.27,14.76
N11450999 on TOP: 72.06,4.93 75.62,8.48 93.47,8.48 94.03,9.04 94.03,12.45 93.47,13 73.61,13 68.22,7.62 52.27,7.62 51.94,7.29 51.94,4.95 51.97,4.93
N11459929 on TOP: 34.14,6.1 37.77,6.1 38.91,7.24 46.2,7.24 46.91,6.53 46.91,5.61 45.36,4.06 34.14,4.06
N11465077 on TOP: 1.55,27.99 1.55,23.27 2.72,22.1 3.63,22.1 4.24,22.71 4.24,27.61 3.2,28.65 2.21,28.65
N11478809 on TOP: 101.96,18.72 101.96,13.77 102.23,13.49 103.56,13.49 103.94,13.87 103.94,18.67 103.5,19.1 102.34,19.1
N11478836 on TOP: 101.88,21.74 101.88,25.22 102.41,25.76 103.53,25.76 104.04,25.25 104.04,21.59 103.61,21.16 102.46,21.16
N11926287 on TOP: 199.42,25.93 199.42,29.21 198.58,30.05 192.04,30.05 189.48,27.48 189.48,26.17 190.96,24.69 198.17,24.69
N11926309 on TOP: 199.47,23.32 199.47,21.49 198.48,20.5 193.27,20.5 192.46,19.68 190.3,19.68 189.48,20.5 189.48,22.4 191.16,24.08 198.7,24.08
N11945881 on TOP: 140.39,22.17 140.39,20.47 140.74,20.12 156.13,20.12 156.57,20.55 156.57,23.34 156.34,23.57 149.63,23.57 147.98,21.92 142.42,21.92 141.99,22.35 140.56,22.35
N11945881 on BOTTOM: 148.87,24.05 148.87,20.65 150.9,18.62 152.53,18.62 152.73,18.41 153.09,18.41 153.29,18.62 153.64,18.62 153.77,18.49 153.77,17.37 156.57,14.58 185.67,14.58 187.35,16.26 187.35,21.16 185.98,22.53 184.58,22.53 183.79,21.74 183.79,19.41 182.69,18.3 162.32,18.3 155.68,24.94 149.76,24.94
N12237167 on TOP: 82.91,5.03 88.44,5.03 88.82,4.65 88.82,2.46 88.47,2.11 83.49,2.11 82.27,3.33 82.27,4.39
N12296601 on TOP: 31.39,9.93 35.59,9.93 36.2,9.32 36.2,8.46 35.59,7.85 32.92,7.85 31.22,6.15 31.22,4.34 30.53,3.66 29.13,3.66 28.27,4.52 28.27,6.81

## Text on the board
Ref Des/Silkscreen Top: TM | DIM- | DIM+ | N | L | 1836 | S/N | DER-742 Rev C | B | A | LYTSwitch 6
User.5: SLOT 1 | SLOT 2 | SLOT 3 | 1.  THROUGH HOLES ARE PLATED THROUGH. | EXCEPTIONS WILL BE NOTED IN DRILL CHART "NOTE". | 2.  MATERIAL: BASE MATERIAL LAMINATED EPOXY | UL APPROVED MANUFACTURED SOURCE FOR FR4. | 3.  SOLDER PLATE WILL BE RoHS COMPLIANT. | 4.  SOLDER MASK LPI (LIQUID PHOTO IMAGEABLE) BOTH SIDES. COLOR GREEN. | SOLDER MASK (REGISTRATION) -0/+0.003" | 5.  SILKSCREEN TOP/BOTTOM SIDE. COLOR WHITE. (MIN.WIDTH 0.005" MAX.WIDTH 0.010") | 6.  FINISH TO BE SMOBC. | 7.  LF HASL. | 8.  BOARD DIMENSION +/- 0.005" | 9.  DRILL TOLERANCE +/- 0.003" | 10. TRACE WIDTH UNDER 0.010" +/- 0.002" | TRACE WIDTH OVER 0.011" +/- 0.005" | 11. TRACE SPACE +/- 0.003" | 12. MATERIAL FR4 COPPER 2 OZ BOARD THICKNESS 0.062" | DELETE THESE HOLES: | NOTES: UNLESS OTHERWISE SPECIFIED
User.8: FIGURE | FINISHED_SIZE | 12.0 | 20.0 | 30.0 | 40.0 | 46.0 | 48.0 | 50.0 | 52.0 | 55.0 | 67.0 | 68.0 | DRILL CHART: TOP to BOTTOM | ALL UNITS ARE IN MILS | PLATED | QTY | 328 | 66 | 2 | 10 | 3 | 9 | 4 | 1 | 7 | 8
